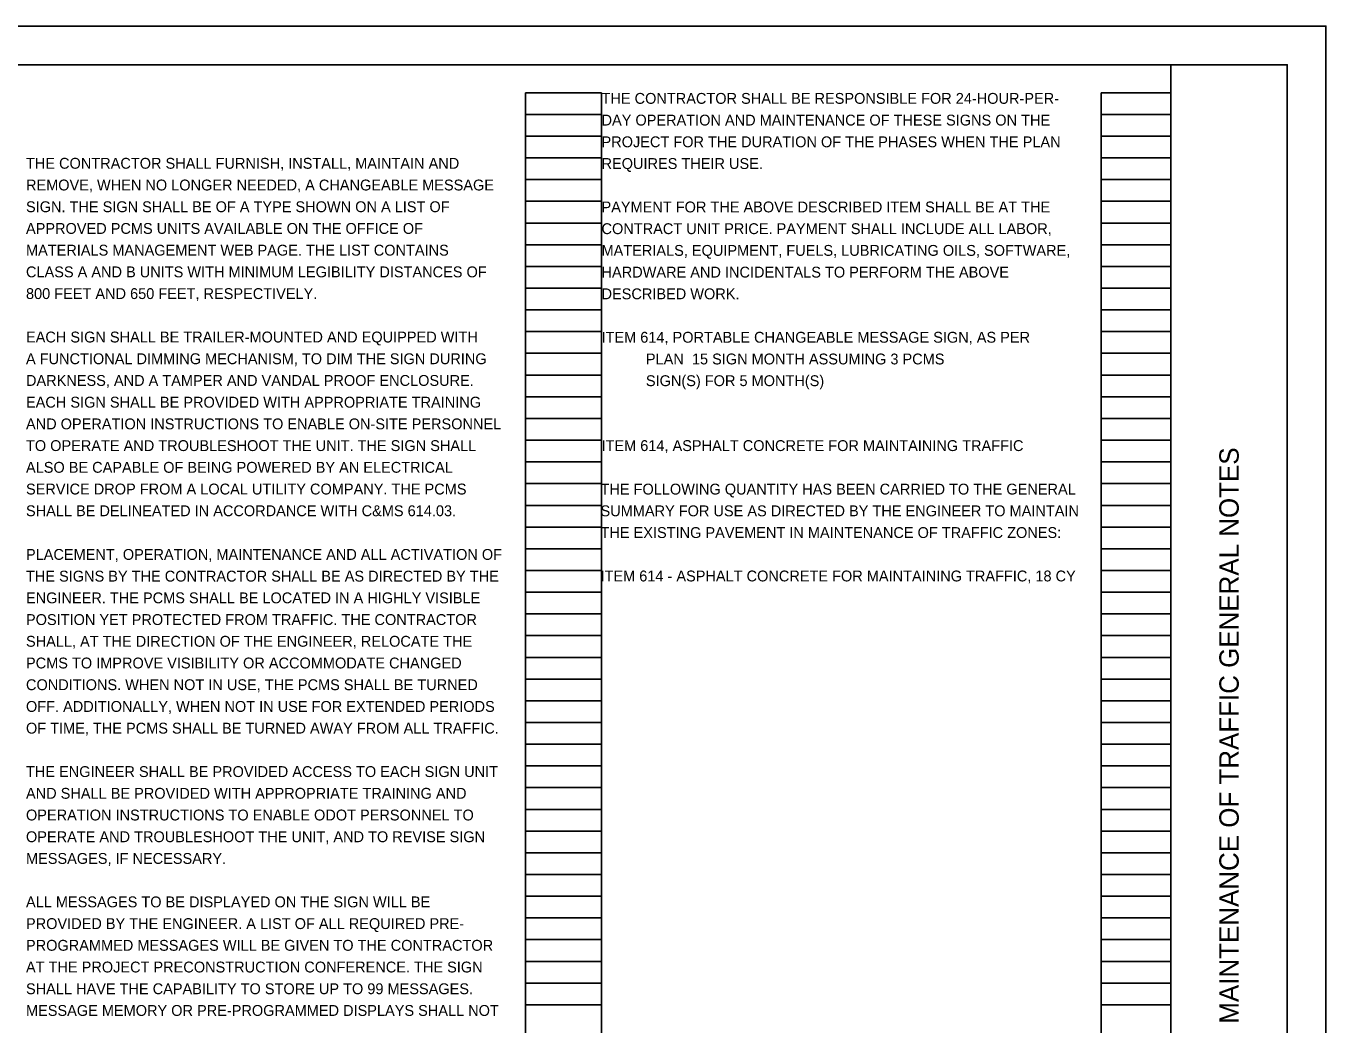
# Model space of a CAD drawing. Extents: x 0.1 to 34.1, y 0.1 to 22.1.
# Drawn here: x 17.32 to 34.08, y 9.23 to 22.1 of the extents above; entities that cross this region are included whole.
import ezdxf

# ---------------------------------------------------------------- set-up
doc = ezdxf.new("R2010")
doc.units = 0
for name, color, linetype in [('SH_Border', 7, 'Continuous'), ('SH_Cut_Line', 7, 'Continuous'), ('SH_Data', 7, 'Continuous'), ('SH_Text', 7, 'Continuous')]:
    doc.layers.add(name, color=color, linetype=linetype)

msp = doc.modelspace()

# ---------------------------------------------------------------- linework, layer by layer
at = {"layer": 'SH_Border'}
msp.add_line((32.076, 0.599), (32.076, 21.599), dxfattribs=at)
msp.add_lwpolyline([(1.576, 21.599), (33.576, 21.599), (33.576, 0.599), (1.576, 0.599)], close=True, dxfattribs=at)
at = {"layer": 'SH_Cut_Line'}
msp.add_lwpolyline([(0.076, 0.099), (34.076, 0.099), (34.076, 22.099), (0.076, 22.099)], close=True, dxfattribs=at)
at = {"layer": 'SH_Data'}
for p, q in [((23.756, 1.079), (23.756, 21.239)), ((23.756, 21.239), (24.736, 21.239)), ((24.736, 1.079), (24.736, 21.239)), ((31.176, 1.079), (31.176, 21.239)), ((31.176, 21.239), (32.076, 21.239)), ((32.076, 1.079), (32.076, 21.239)), ((23.756, 20.959), (24.736, 20.959)), ((31.176, 20.959), (32.076, 20.959)), ((23.756, 20.679), (24.736, 20.679)), ((31.176, 20.679), (32.076, 20.679)), ((23.756, 20.399), (24.736, 20.399)), ((31.176, 20.399), (32.076, 20.399)), ((23.756, 20.119), (24.736, 20.119)), ((31.176, 20.119), (32.076, 20.119)), ((23.756, 19.839), (24.736, 19.839)), ((31.176, 19.839), (32.076, 19.839)), ((23.756, 19.559), (24.736, 19.559)), ((31.176, 19.559), (32.076, 19.559)), ((23.756, 19.279), (24.736, 19.279)), ((31.176, 19.279), (32.076, 19.279)), ((23.756, 18.999), (24.736, 18.999)), ((31.176, 18.999), (32.076, 18.999)), ((23.756, 18.719), (24.736, 18.719)), ((31.176, 18.719), (32.076, 18.719)), ((23.756, 18.439), (24.736, 18.439)), ((31.176, 18.439), (32.076, 18.439)), ((23.756, 18.159), (24.736, 18.159)), ((31.176, 18.159), (32.076, 18.159)), ((23.756, 17.879), (24.736, 17.879)), ((31.176, 17.879), (32.076, 17.879)), ((23.756, 17.599), (24.736, 17.599)), ((31.176, 17.599), (32.076, 17.599)), ((23.756, 17.319), (24.736, 17.319)), ((31.176, 17.319), (32.076, 17.319)), ((23.756, 17.039), (24.736, 17.039)), ((31.176, 17.039), (32.076, 17.039)), ((23.756, 16.759), (24.736, 16.759)), ((31.176, 16.759), (32.076, 16.759)), ((23.756, 16.479), (24.736, 16.479)), ((31.176, 16.479), (32.076, 16.479)), ((23.756, 16.199), (24.736, 16.199)), ((31.176, 16.199), (32.076, 16.199)), ((23.756, 15.919), (24.736, 15.919)), ((31.176, 15.919), (32.076, 15.919)), ((23.756, 15.639), (24.736, 15.639)), ((31.176, 15.639), (32.076, 15.639)), ((23.756, 15.359), (24.736, 15.359)), ((31.176, 15.359), (32.076, 15.359)), ((23.756, 15.079), (24.736, 15.079)), ((31.176, 15.079), (32.076, 15.079)), ((23.756, 14.799), (24.736, 14.799)), ((31.176, 14.799), (32.076, 14.799)), ((23.756, 14.519), (24.736, 14.519)), ((31.176, 14.519), (32.076, 14.519)), ((23.756, 14.239), (24.736, 14.239)), ((31.176, 14.239), (32.076, 14.239)), ((23.756, 13.959), (24.736, 13.959)), ((31.176, 13.959), (32.076, 13.959)), ((23.756, 13.679), (24.736, 13.679)), ((31.176, 13.679), (32.076, 13.679)), ((23.756, 13.399), (24.736, 13.399)), ((31.176, 13.399), (32.076, 13.399)), ((23.756, 13.119), (24.736, 13.119)), ((31.176, 13.119), (32.076, 13.119)), ((23.756, 12.839), (24.736, 12.839)), ((31.176, 12.839), (32.076, 12.839)), ((23.756, 12.559), (24.736, 12.559)), ((31.176, 12.559), (32.076, 12.559)), ((23.756, 12.279), (24.736, 12.279)), ((31.176, 12.279), (32.076, 12.279)), ((23.756, 11.999), (24.736, 11.999)), ((31.176, 11.999), (32.076, 11.999)), ((23.756, 11.719), (24.736, 11.719)), ((31.176, 11.719), (32.076, 11.719)), ((23.756, 11.439), (24.736, 11.439)), ((31.176, 11.439), (32.076, 11.439)), ((23.756, 11.159), (24.736, 11.159)), ((31.176, 11.159), (32.076, 11.159)), ((23.756, 10.879), (24.736, 10.879)), ((31.176, 10.879), (32.076, 10.879)), ((23.756, 10.599), (24.736, 10.599)), ((31.176, 10.599), (32.076, 10.599)), ((23.756, 10.319), (24.736, 10.319)), ((31.176, 10.319), (32.076, 10.319)), ((23.756, 10.039), (24.736, 10.039)), ((31.176, 10.039), (32.076, 10.039)), ((23.756, 9.759), (24.736, 9.759)), ((31.176, 9.759), (32.076, 9.759)), ((23.756, 9.479), (24.736, 9.479)), ((31.176, 9.479), (32.076, 9.479))]:
    msp.add_line(p, q, dxfattribs=at)

# ---------------------------------------------------------------- texts
msp.add_text('MAINTENANCE OF TRAFFIC GENERAL NOTES', height=0.25, rotation=90, dxfattribs=at).set_placement((32.951, 9.236))
at = {"layer": 'SH_Text'}
for s, p in [('THE CONTRACTOR SHALL BE RESPONSIBLE FOR 24-HOUR-PER-', (24.736, 21.096)), ('DAY OPERATION AND MAINTENANCE OF THESE SIGNS ON THE', (24.736, 20.816)), ('PROJECT FOR THE DURATION OF THE PHASES WHEN THE PLAN', (24.736, 20.536)), ('THE CONTRACTOR SHALL FURNISH, INSTALL, MAINTAIN AND', (17.316, 20.259)), ('REQUIRES THEIR USE.', (24.736, 20.256)), ('REMOVE, WHEN NO LONGER NEEDED, A CHANGEABLE MESSAGE', (17.316, 19.979)), ('SIGN. THE SIGN SHALL BE OF A TYPE SHOWN ON A LIST OF', (17.316, 19.699)), ('PAYMENT FOR THE ABOVE DESCRIBED ITEM SHALL BE AT THE', (24.736, 19.696)), ('APPROVED PCMS UNITS AVAILABLE ON THE OFFICE OF', (17.316, 19.419)), ('CONTRACT UNIT PRICE. PAYMENT SHALL INCLUDE ALL LABOR,', (24.736, 19.416)), ('MATERIALS MANAGEMENT WEB PAGE. THE LIST CONTAINS', (17.316, 19.139)), ('MATERIALS, EQUIPMENT, FUELS, LUBRICATING OILS, SOFTWARE,', (24.736, 19.136)), ('CLASS A AND B UNITS WITH MINIMUM LEGIBILITY DISTANCES OF', (17.316, 18.859)), ('HARDWARE AND INCIDENTALS TO PERFORM THE ABOVE', (24.736, 18.856)), ('800 FEET AND 650 FEET, RESPECTIVELY.', (17.316, 18.579)), ('DESCRIBED WORK.', (24.736, 18.576)), ('EACH SIGN SHALL BE TRAILER-MOUNTED AND EQUIPPED WITH', (17.316, 18.019)), ('ITEM 614, PORTABLE CHANGEABLE MESSAGE SIGN, AS PER', (24.736, 18.016)), ('A FUNCTIONAL DIMMING MECHANISM, TO DIM THE SIGN DURING', (17.316, 17.739)), ('           PLAN  15 SIGN MONTH ASSUMING 3 PCMS', (24.736, 17.736)), ('DARKNESS, AND A TAMPER AND VANDAL PROOF ENCLOSURE.', (17.316, 17.459)), ('           SIGN(S) FOR 5 MONTH(S)', (24.736, 17.456)), ('EACH SIGN SHALL BE PROVIDED WITH APPROPRIATE TRAINING', (17.316, 17.179)), ('AND OPERATION INSTRUCTIONS TO ENABLE ON-SITE PERSONNEL', (17.316, 16.899)), ('TO OPERATE AND TROUBLESHOOT THE UNIT. THE SIGN SHALL', (17.316, 16.619)), ('ITEM 614, ASPHALT CONCRETE FOR MAINTAINING TRAFFIC', (24.736, 16.619)), ('ALSO BE CAPABLE OF BEING POWERED BY AN ELECTRICAL', (17.316, 16.339)), ('SERVICE DROP FROM A LOCAL UTILITY COMPANY. THE PCMS', (17.316, 16.059)), ('THE FOLLOWING QUANTITY HAS BEEN CARRIED TO THE GENERAL ', (24.723, 16.058)), ('SHALL BE DELINEATED IN ACCORDANCE WITH C&MS 614.03.', (17.316, 15.779)), ('SUMMARY FOR USE AS DIRECTED BY THE ENGINEER TO MAINTAIN ', (24.723, 15.778)), ('THE EXISTING PAVEMENT IN MAINTENANCE OF TRAFFIC ZONES:', (24.723, 15.498)), ('PLACEMENT, OPERATION, MAINTENANCE AND ALL ACTIVATION OF', (17.316, 15.216)), ('THE SIGNS BY THE CONTRACTOR SHALL BE AS DIRECTED BY THE', (17.316, 14.936)), ('ITEM 614 - ASPHALT CONCRETE FOR MAINTAINING TRAFFIC, 18 CY', (24.723, 14.938)), ('ENGINEER. THE PCMS SHALL BE LOCATED IN A HIGHLY VISIBLE', (17.316, 14.656)), ('POSITION YET PROTECTED FROM TRAFFIC. THE CONTRACTOR', (17.316, 14.376)), ('SHALL, AT THE DIRECTION OF THE ENGINEER, RELOCATE THE', (17.316, 14.096)), ('PCMS TO IMPROVE VISIBILITY OR ACCOMMODATE CHANGED', (17.316, 13.816)), ('CONDITIONS. WHEN NOT IN USE, THE PCMS SHALL BE TURNED', (17.316, 13.536)), ('OFF. ADDITIONALLY, WHEN NOT IN USE FOR EXTENDED PERIODS', (17.316, 13.256)), ('OF TIME, THE PCMS SHALL BE TURNED AWAY FROM ALL TRAFFIC.', (17.316, 12.976)), ('THE ENGINEER SHALL BE PROVIDED ACCESS TO EACH SIGN UNIT', (17.316, 12.416)), ('AND SHALL BE PROVIDED WITH APPROPRIATE TRAINING AND', (17.316, 12.136)), ('OPERATION INSTRUCTIONS TO ENABLE ODOT PERSONNEL TO', (17.316, 11.856)), ('OPERATE AND TROUBLESHOOT THE UNIT, AND TO REVISE SIGN', (17.316, 11.576)), ('MESSAGES, IF NECESSARY.', (17.316, 11.296)), ('ALL MESSAGES TO BE DISPLAYED ON THE SIGN WILL BE', (17.316, 10.736)), ('PROVIDED BY THE ENGINEER. A LIST OF ALL REQUIRED PRE-', (17.316, 10.456)), ('PROGRAMMED MESSAGES WILL BE GIVEN TO THE CONTRACTOR', (17.316, 10.176)), ('AT THE PROJECT PRECONSTRUCTION CONFERENCE. THE SIGN', (17.316, 9.896)), ('SHALL HAVE THE CAPABILITY TO STORE UP TO 99 MESSAGES.', (17.316, 9.616)), ('MESSAGE MEMORY OR PRE-PROGRAMMED DISPLAYS SHALL NOT', (17.316, 9.336))]:
    msp.add_text(s, height=0.14, dxfattribs=at).set_placement(p)

doc.saveas('drawing.dxf')
